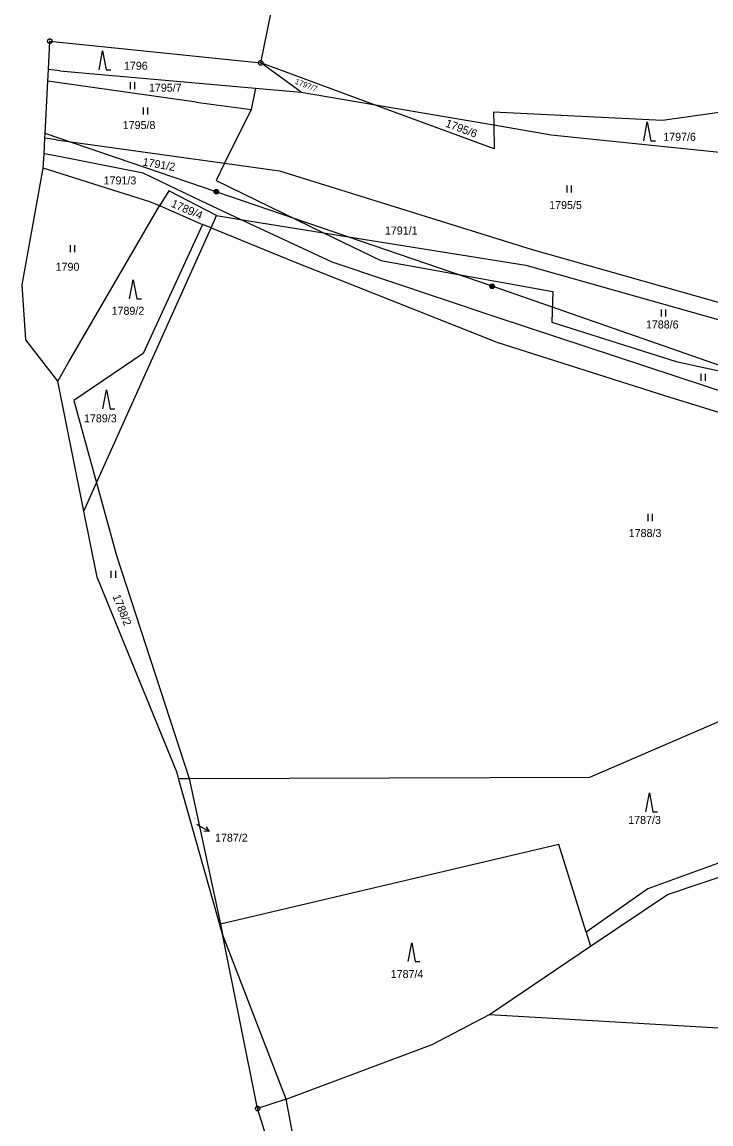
# Model space of a CAD drawing. Extents: x -609861 to -605046, y -1120287 to -1116307.
# Drawn here: x -609276.6 to -609130.1, y -1117954.9 to -1117720.7 of the extents above; entities that cross this region are included whole.
import ezdxf

# ---------------------------------------------------------------- set-up
doc = ezdxf.new("R2010")
doc.units = 0
for name, color, linetype in [('Vrstva 1', 7, 'Continuous'), ('Vrstva 2', 7, 'Continuous'), ('Vrstva 3', 7, 'Continuous'), ('Vrstva 4', 7, 'Continuous'), ('Vrstva 6', 7, 'Continuous'), ('Vrstva 7', 7, 'Continuous'), ('Vrstva 8', 7, 'Continuous')]:
    doc.layers.add(name, color=color, linetype=linetype)

msp = doc.modelspace()

# ---------------------------------------------------------------- linework, layer by layer
at = {"layer": 'Vrstva 1'}
for p, q in [((-609225.88, -1117729.4), (-609218.81, -1117694.79)), ((-609271.02, -1117730.83), (-609270.71, -1117724.79)), ((-609270.71, -1117724.79), (-609225.88, -1117729.4)), ((-609271.15, -1117733.28), (-609271.02, -1117730.83)), ((-609268.58, -1117731.05), (-609271.02, -1117730.83)), ((-609201.87, -1117738.23), (-609225.88, -1117729.4)), ((-609217.28, -1117735.59), (-609225.88, -1117729.4)), ((-609268.58, -1117731.05), (-609226.97, -1117734.73)), ((-609271.72, -1117744.42), (-609271.15, -1117733.28)), ((-609239.58, -1117737.73), (-609271.15, -1117733.28)), ((-609226.97, -1117734.73), (-609227.91, -1117739.32)), ((-609226.97, -1117734.73), (-609217.28, -1117735.59)), ((-609217.28, -1117735.59), (-609201.87, -1117738.23)), ((-609239.58, -1117737.73), (-609227.91, -1117739.32)), ((-609103.48, -1117736.49), (-609140.42, -1117741.63)), ((-609227.91, -1117739.32), (-609233.55, -1117750.7)), ((-609176.22, -1117747.65), (-609201.87, -1117738.23)), ((-609201.87, -1117738.23), (-609176.34, -1117742.59)), ((-609140.42, -1117741.63), (-609176.41, -1117739.85)), ((-609176.41, -1117739.85), (-609176.34, -1117742.59)), ((-609176.34, -1117742.59), (-609176.22, -1117747.65)), ((-609176.34, -1117742.59), (-609164.11, -1117744.68)), ((-609271.77, -1117745.41), (-609271.72, -1117744.42)), ((-609164.11, -1117744.68), (-609122.76, -1117748.93)), ((-609271.94, -1117748.72), (-609271.77, -1117745.41)), ((-609269.28, -1117745.75), (-609271.77, -1117745.41)), ((-609269.28, -1117745.75), (-609233.55, -1117750.7)), ((-609272.12, -1117751.73), (-609271.94, -1117748.72)), ((-609269.53, -1117749.14), (-609271.94, -1117748.72)), ((-609250.88, -1117752.79), (-609269.53, -1117749.14)), ((-609276.64, -1117776.58), (-609272.12, -1117751.73)), ((-609249.48, -1117758.94), (-609272.12, -1117751.73)), ((-609233.55, -1117750.7), (-609235.37, -1117754.38)), ((-609233.55, -1117750.7), (-609221.9, -1117752.31)), ((-609238.44, -1117758.81), (-609250.88, -1117752.79)), ((-609221.9, -1117752.31), (-609168.18, -1117769.05)), ((-609245.4, -1117756.57), (-609247.44, -1117759.74)), ((-609235.25, -1117761.84), (-609245.4, -1117756.57)), ((-609235.37, -1117754.38), (-609212.53, -1117765.47)), ((-609247.44, -1117759.74), (-609249.48, -1117758.94)), ((-609230.21, -1117762.64), (-609238.44, -1117758.81)), ((-609266.66, -1117792.95), (-609247.44, -1117759.74)), ((-609247.44, -1117759.74), (-609247.29, -1117759.8)), ((-609247.29, -1117759.8), (-609238.25, -1117763.72)), ((-609236.43, -1117764.46), (-609235.25, -1117761.84)), ((-609235.25, -1117761.84), (-609230.21, -1117762.64)), ((-609210.68, -1117771.75), (-609230.21, -1117762.64)), ((-609230.21, -1117762.64), (-609212.53, -1117765.47)), ((-609260.78, -1117818.65), (-609236.43, -1117764.46)), ((-609238.25, -1117763.72), (-609250.86, -1117791.11)), ((-609236.43, -1117764.46), (-609238.25, -1117763.72)), ((-609236.43, -1117764.46), (-609218.53, -1117771.75)), ((-609212.53, -1117765.47), (-609200.34, -1117771.39)), ((-609212.53, -1117765.47), (-609169.53, -1117772.34)), ((-609168.18, -1117769.05), (-609115.07, -1117784.1)), ((-609218.53, -1117771.75), (-609175.65, -1117788.76)), ((-609175.84, -1117783.44), (-609210.68, -1117771.75)), ((-609200.34, -1117771.39), (-609163.78, -1117777.95)), ((-609169.53, -1117772.34), (-609114.95, -1117787.8)), ((-609275.83, -1117788.27), (-609276.64, -1117776.58)), ((-609163.78, -1117777.95), (-609163.97, -1117784.5)), ((-609116.43, -1117802.97), (-609175.84, -1117783.44)), ((-609163.97, -1117784.5), (-609137.55, -1117792.83)), ((-609269.04, -1117797.02), (-609275.83, -1117788.27)), ((-609175.65, -1117788.76), (-609140.04, -1117800.1)), ((-609250.86, -1117791.11), (-609265.59, -1117801.14)), ((-609269.04, -1117797.02), (-609266.66, -1117792.95)), ((-609137.55, -1117792.83), (-609115.58, -1117797.61)), ((-609263.48, -1117824.65), (-609269.04, -1117797.02)), ((-609265.59, -1117801.14), (-609260.78, -1117818.65)), ((-609140.04, -1117800.1), (-609117.64, -1117807.01)), ((-609263.48, -1117824.65), (-609260.78, -1117818.65)), ((-609260.78, -1117818.65), (-609256.55, -1117834.07)), ((-609260.66, -1117838.65), (-609263.48, -1117824.65)), ((-609256.55, -1117834.07), (-609241.12, -1117881.43)), ((-609243.68, -1117880.22), (-609260.66, -1117838.65)), ((-609155.91, -1117881.2), (-609122.18, -1117866.61)), ((-609243.34, -1117881.43), (-609243.68, -1117880.22)), ((-609233.98, -1117914.53), (-609243.34, -1117881.43)), ((-609243.34, -1117881.43), (-609241.12, -1117881.43)), ((-609241.12, -1117881.43), (-609155.91, -1117881.2)), ((-609241.12, -1117881.43), (-609234.44, -1117912.41)), ((-609162.45, -1117895.47), (-609234.44, -1117912.41)), ((-609156.67, -1117914.09), (-609162.45, -1117895.47)), ((-609119.49, -1117896.1), (-609143.56, -1117904.9)), ((-609139.4, -1117906.07), (-609109.24, -1117895.99)), ((-609143.56, -1117904.9), (-609156.67, -1117914.09)), ((-609155.74, -1117917.1), (-609139.4, -1117906.07)), ((-609234.44, -1117912.41), (-609233.98, -1117914.53)), ((-609226.54, -1117951.58), (-609233.98, -1117914.53)), ((-609156.67, -1117914.09), (-609155.74, -1117917.1)), ((-609177.21, -1117931.59), (-609155.74, -1117917.1)), ((-609189.41, -1117938.01), (-609177.21, -1117931.59)), ((-609177.21, -1117931.59), (-609123.13, -1117934.76)), ((-609220.48, -1117949.56), (-609189.41, -1117938.01)), ((-609220.48, -1117949.56), (-609226.54, -1117951.58)), ((-609220.56, -1117970.6), (-609226.54, -1117951.58))]:
    msp.add_line(p, q, dxfattribs=at)
at = {"layer": 'Vrstva 3'}
for p, q in [((-609253.66, -1117733.48), (-609253.66, -1117734.98)), ((-609252.66, -1117734.98), (-609252.66, -1117733.48)), ((-609250.89, -1117738.86), (-609250.89, -1117740.36)), ((-609249.89, -1117740.36), (-609249.89, -1117738.86)), ((-609160.8, -1117755.43), (-609160.8, -1117756.93)), ((-609159.8, -1117756.93), (-609159.8, -1117755.43)), ((-609266.41, -1117768.14), (-609266.41, -1117769.64)), ((-609265.41, -1117769.64), (-609265.41, -1117768.14)), ((-609140.74, -1117781.79), (-609140.74, -1117783.29)), ((-609139.74, -1117783.29), (-609139.74, -1117781.79)), ((-609132.32, -1117795.47), (-609132.32, -1117796.97)), ((-609131.32, -1117796.97), (-609131.32, -1117795.47)), ((-609143.56, -1117825.24), (-609143.56, -1117826.74)), ((-609142.56, -1117826.74), (-609142.56, -1117825.24)), ((-609257.72, -1117837.33), (-609257.72, -1117838.83)), ((-609256.72, -1117838.83), (-609256.72, -1117837.33))]:
    msp.add_line(p, q, dxfattribs=at)
for points in [[(-609260.25, -1117730.85), (-609259.5, -1117726.85), (-609258.75, -1117730.85), (-609257.75, -1117730.85)], [(-609144.43, -1117745.95), (-609143.68, -1117741.95), (-609142.93, -1117745.95), (-609141.93, -1117745.95)], [(-609253.76, -1117779.52), (-609253.01, -1117775.52), (-609252.26, -1117779.52), (-609251.26, -1117779.52)], [(-609259.43, -1117802.89), (-609258.68, -1117798.89), (-609257.93, -1117802.89), (-609256.93, -1117802.89)], [(-609143.98, -1117888.53), (-609143.23, -1117884.53), (-609142.48, -1117888.53), (-609141.48, -1117888.53)], [(-609194.53, -1117920.35), (-609193.78, -1117916.35), (-609193.03, -1117920.35), (-609192.03, -1117920.35)]]:
    msp.add_lwpolyline(points, dxfattribs=at)
at = {"layer": 'Vrstva 4'}
for p, q in [((-609220.48, -1117949.56), (-609233.98, -1117914.53)), ((-609216.71, -1117969.81), (-609220.48, -1117949.56))]:
    msp.add_line(p, q, dxfattribs=at)
at = {"layer": 'Vrstva 6'}
for p, q in [((-609235.32, -1117756.79), (-609271.72, -1117744.42)), ((-609176.69, -1117776.87), (-609235.32, -1117756.79)), ((-609116.98, -1117797.68), (-609176.69, -1117776.87))]:
    msp.add_line(p, q, dxfattribs=at)
for points in [[(-609235.47, -1117756.31), (-609235.16, -1117756.31), (-609234.91, -1117756.49), (-609234.81, -1117756.78), (-609234.91, -1117757.07), (-609235.16, -1117757.25), (-609235.47, -1117757.25), (-609235.72, -1117757.07), (-609235.82, -1117756.78), (-609235.72, -1117756.49), (-609235.47, -1117756.31), (-609235.44, -1117756.35), (-609235.2, -1117756.35), (-609235.04, -1117756.43), (-609235.6, -1117756.43), (-609235.68, -1117756.51), (-609234.96, -1117756.51), (-609234.96, -1117756.59), (-609235.68, -1117756.59), (-609235.72, -1117756.67), (-609234.92, -1117756.67), (-609234.88, -1117756.75), (-609235.76, -1117756.75), (-609235.76, -1117756.83), (-609234.88, -1117756.83), (-609234.91, -1117756.91), (-609235.72, -1117756.91), (-609235.71, -1117756.99), (-609234.9, -1117756.99), (-609234.95, -1117757.07), (-609235.67, -1117757.07), (-609235.59, -1117757.15), (-609235.03, -1117757.15), (-609235.14, -1117757.23), (-609235.48, -1117757.23)], [(-609176.84, -1117776.39), (-609176.53, -1117776.39), (-609176.28, -1117776.57), (-609176.18, -1117776.86), (-609176.28, -1117777.15), (-609176.53, -1117777.33), (-609176.84, -1117777.33), (-609177.09, -1117777.15), (-609177.19, -1117776.86), (-609177.09, -1117776.57), (-609176.84, -1117776.39), (-609176.81, -1117776.43), (-609176.57, -1117776.43), (-609176.41, -1117776.51), (-609176.97, -1117776.51), (-609177.05, -1117776.59), (-609176.33, -1117776.59), (-609176.33, -1117776.67), (-609177.05, -1117776.67), (-609177.09, -1117776.75), (-609176.29, -1117776.75), (-609176.25, -1117776.83), (-609177.13, -1117776.83), (-609177.13, -1117776.91), (-609176.25, -1117776.91), (-609176.28, -1117776.99), (-609177.09, -1117776.99), (-609177.08, -1117777.07), (-609176.27, -1117777.07), (-609176.32, -1117777.15), (-609177.04, -1117777.15), (-609176.96, -1117777.23), (-609176.4, -1117777.23), (-609176.51, -1117777.31), (-609176.85, -1117777.31)]]:
    msp.add_lwpolyline(points, dxfattribs=at)
at = {"layer": 'Vrstva 7'}
msp.add_line((-609236.853, -1117892.684), (-609239.46, -1117891.2), dxfattribs=at)
msp.add_lwpolyline([(-609237.474, -1117891.755), (-609236.853, -1117892.684), (-609237.969, -1117892.624)], dxfattribs=at)
at = {"layer": 'Vrstva 8'}
for p, q in [((-609270.83, -1117724.79), (-609270.59, -1117724.79)), ((-609226, -1117729.4), (-609225.76, -1117729.4)), ((-609226.66, -1117951.58), (-609226.42, -1117951.58))]:
    msp.add_line(p, q, dxfattribs=at)
for points in [[(-609270.56, -1117724.31), (-609270.31, -1117724.49), (-609270.21, -1117724.78), (-609270.31, -1117725.07), (-609270.56, -1117725.25), (-609270.87, -1117725.25), (-609271.12, -1117725.07), (-609271.22, -1117724.78), (-609271.12, -1117724.49), (-609270.87, -1117724.31)], [(-609225.73, -1117728.92), (-609225.48, -1117729.1), (-609225.38, -1117729.39), (-609225.48, -1117729.68), (-609225.73, -1117729.86), (-609226.04, -1117729.86), (-609226.29, -1117729.68), (-609226.39, -1117729.39), (-609226.29, -1117729.1), (-609226.04, -1117728.92)], [(-609226.39, -1117951.1), (-609226.14, -1117951.28), (-609226.04, -1117951.57), (-609226.14, -1117951.86), (-609226.39, -1117952.04), (-609226.7, -1117952.04), (-609226.95, -1117951.86), (-609227.05, -1117951.57), (-609226.95, -1117951.28), (-609226.7, -1117951.1)]]:
    msp.add_lwpolyline(points, close=True, dxfattribs=at)

# ---------------------------------------------------------------- texts
at = {"layer": 'Vrstva 2'}
for s, height, p in [('1796', 1.7, (-609254.967, -1117730.85)), ('1795/7', 1.7, (-609249.647, -1117735.51)), ('1795/8', 1.7, (-609255.227, -1117743.45)), ('1797/6', 1.7, (-609140.287, -1117745.95)), ('1791/3', 1.7, (-609259.287, -1117755.22)), ('1795/5', 1.7, (-609164.537, -1117760.45)), ('1791/1', 1.7, (-609199.477, -1117765.86)), ('1790', 1.7, (-609269.497, -1117773.56)), ('1789/2', 1.7, (-609257.597, -1117782.92)), ('1788/6', 1.7, (-609143.967, -1117785.83)), ('1789/3', 1.7, (-609263.467, -1117805.77)), ('1788/3', 1.7, (-609147.627, -1117830.15)), ('1787/2', 0.2, (-609240.314, -1117890.09)), ('1787/3', 1.7, (-609147.737, -1117891.11)), ('1787/4', 1.7, (-609198.237, -1117923.84))]:
    msp.add_text(s, height=height, dxfattribs=at).set_placement(p)
for s, height, rotation, p in [('1797/7', 1.2, 339.30561, (-609218.711, -1117733.808)), ('1795/6', 1.7, 339.30561, (-609186.743, -1117742.889)), ('1791/2', 1.7, 350.07721, (-609251.083, -1117751.198)), ('1789/4', 1.7, 336.61271, (-609245.08, -1117759.906)), ('1788/2', 1.7, 291.57822, (-609257.416, -1117842.735))]:
    msp.add_text(s, height=height, rotation=rotation, dxfattribs=at).set_placement(p)
at = {"layer": 'Vrstva 7'}
msp.add_text('1787/2', height=1.7, dxfattribs=at).set_placement((-609235.597, -1117894.88))

doc.saveas('drawing.dxf')
